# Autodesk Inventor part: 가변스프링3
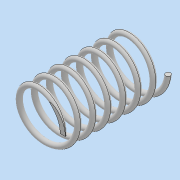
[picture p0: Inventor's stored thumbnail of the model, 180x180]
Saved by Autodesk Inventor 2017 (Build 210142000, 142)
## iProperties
Part Number: 가변스프링3
Material: 일반
Document SubType Name: Modeling
Designer: MRC
Density: 1 g/cm^3
Appearance: 기본값
Author: MRC
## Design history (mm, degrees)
sketch "스케치1"
  geometry: L1 (0, 41.411)-(10, 41.411); L2 (10, 41.411)-(10, 0); L3 (10, 0)-(0, 0); L4 (0, 0)-(0, 41.411); C1 r 1 at (10, 0); 1 further point
  constraints: 8 end point, 2 coincident, 2 parallel, 1 centre point, 1 horizontal, 1 perpendicular
  dimensions: "d0" = 41.4112 distance of L1.end L2.end (derived); "d1" = 20 diameter of L2 L4; "d2" = 2 diameter of C1
feature "코일1" sketch "스케치1" pitch "d3" = 10; turns "d5" = 7; dims "d4" = 41.4112 (= d0), "d6" = 0, angle "d7" = 90 deg, angle "d8" = 90 deg, "d9" = 0, "d10" = 0
sketch "스케치2"
  geometry: L1 (-19.444, 50)-(19.444, 50); L2 (19.444, 50)-(19.444, 0); L3 (19.444, 0)-(-19.444, 0); L4 (-19.444, 0)-(-19.444, 50); 2 further points
  constraints: 8 end point, 2 parallel, 1 coincident, 1 horizontal, 1 midpoint, 1 perpendicular
  dimensions: "d11" = 50 distance of L1.end L2.end; "d12" = 38.88889 distance of L1.start L1.end
extrude "돌출1" sketch "스케치2" stored distance "d13" = 0; taper "d14" = 0 deg
node "솔리드1"
